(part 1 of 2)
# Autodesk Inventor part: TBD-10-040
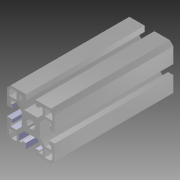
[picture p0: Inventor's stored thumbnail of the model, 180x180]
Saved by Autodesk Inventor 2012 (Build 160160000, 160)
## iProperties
Created: 2004-10
Document SubType Name: Modeling
Designer: Autodesk, Inc.
Manufacturer: Standard
Standards Organization: Custom
Material: Aluminum-6061
Stock Number: 10-040
Description: 40 SERIES, 40X40, STANDARD PROFILE
Catalog Web Link: http://www.parker.com/ead/cm1.asp?cmid=809
Vendor: PARKER IPS
Part Number: TBD-10-040
Mass: 179.948 g
Surface Area: 483.565 cm^2
Volume: 66.4013 cm^3
Density: 2.71 g/cm^3
CAGE: 1LJX3
Dept. ID: Product Design
Description #2: ---
Finish #1: ---
Finish #2: ---
Material ID: ---
Project Number: ---
Length: 100.000 mm
Author: Autodesk, Inc.
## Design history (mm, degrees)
sketch "40 Series Base"
  geometry: L1 (-17, 20)-(17, 20); L2 (20, 17)-(20, -17); L3 (17, -20)-(-17, -20); L4 (-20, -17)-(-20, 17); L5 (-17, 20)-(-20, 17); L6 (17, 20)-(20, 17); L7 (20, -17)-(17, -20); L8 (-17, -20)-(-20, -17); C1 r 3.4 at (0, 0); 7 further points
  constraints: 16 end point, 8 point on line, 2 midpoint, 2 parallel, 1 centre point, 1 horizontal, 1 horizontal alignment, 1 perpendicular, 1 vertical alignment
  dimensions: "Height" = 40 distance of point (-20, -20) point (-20, 20); "Width" = 40 distance of point (-20, 20) point (20, 20); "d9" = 3 distance of L1.start point (-20, 20); "d10" = 3 distance of L4.end point (-20, 20) (= d9); "d11" = 3 distance of L1.end point (20, 20) (= d9); "d12" = 3 distance of L2.start point (20, 20) (= d11); "d13" = 3 distance of L2.end point (20, -20) (= d9); "d14" = 3 distance of L3.start point (20, -20) (= d13); "d15" = 3 distance of L3.end point (-20, -20) (= d9); "d16" = 3 distance of L4.start point (-20, -20) (= d15); "CenterX" = 20 distance from line of C1.centre L4; "CenterY" = 20 distance from line of L3 C1.centre; "Center_Dia" = 6.8 diameter of C1
extrude "Base Extrusion" new body sketch "40 Series Base" taper "d21" = 0 deg; stored distance "Length" = 100
extrude "CenterHole" cut sketch "40 Series Base" stored distance "d22" = 100; taper "d23" = 0 deg
sketch "Sketch5"
  geometry: L1 (17, -20)-(-17, -20) reference; L2 (-20, -17)-(-20, 17) reference; L3 (3.375, -7.75)-(-3.375, -7.75); L4 (4, -15.5)-(10, -15.5); L5 (10, -15.5)-(10, -14.177); L6 (10, -14.177)-(3.375, -7.75); L7 (4, -20)-(4, -15.5); L8 (-4, -20)-(4, -20); L9 (-4, -15.5)-(-4, -20); L10 (-3.375, -7.75)-(-10, -14.177); L11 (-10, -14.177)-(-10, -15.5); L12 (-10, -15.5)-(-4, -15.5); L13 (0, -7.75)-(0, -20)
  constraints: 22 end point, 2 collinear, 2 midpoint, 1 vertical, 3 other
  dimensions: "d24" = 20 distance between parallel lines of L5 L11; "d25" = 6.75 distance of L3.start L3.end; "d26" = 4.5 distance between parallel lines of L8 L12; "d27" = 1.32302 distance of L10.end L11.end; "d28" = 8 distance between parallel lines of L7 L9; "d29" = 20 distance between parallel lines of L13 L2; "d30" = 12.25 distance of L13.start L13.end; "d31" = 4.5 distance between parallel lines of L8 L4 (derived)
extrude "Standard Slot X" cut sketch "Sketch5" stored distance "d32" = 100; taper "d33" = 0 deg
sketch "Sketch6"
  geometry: L1 (-20, -17)-(-20, 17) reference; L2 (17, -20)-(-17, -20) reference; L3 (-20, 4)-(-15.5, 4); L4 (-15.5, 4)-(-15.5, 10); L5 (-15.5, 10)-(-14.177, 10); L6 (-14.177, 10)-(-7.75, 3.375); L7 (-7.75, 3.375)-(-7.75, -3.375); L8 (-7.75, -3.375)-(-14.177, -10); L9 (-14.177, -10)-(-15.5, -10); L10 (-15.5, -10)-(-15.5, -4); L11 (-15.5, -4)-(-20, -4); L12 (-20, 4)-(-20, -4); L13 (-7.75, 0)-(-20, 0)
  constraints: 22 end point, 4 parallel, 2 collinear, 2 midpoint, 2 perpendicular, 2 point on line, 1 horizontal, 3 other
  dimensions: "d34" = 8 distance between parallel lines of L11 L3 (= d28); "d35" = 4.5 distance of L3.start L3.end (= d26); "d36" = 1.32302 distance of L4.end L5.end (= d27); "d37" = 12.25 distance between parallel lines of L12 L7 (= d30); "d38" = 20 distance between parallel lines of L9 L5 (= d24); "d39" = 6.75 distance of L6.end L7.end (= d25); "d40" = 20 distance between parallel lines of L2 L13
extrude "Standard Slot Y" cut sketch "Sketch6" stored distance "d41" = 100; taper "d42" = 0 deg
pattern_linear "Slot X Pattern" dims "d87" = 40
pattern_linear "Slot Y Pattern" dims "d67" = 40
mirror "Mirror Slot X"
mirror "Mirror Slot Y"
pattern_linear "CenterHole Pattern" dims "d70" = 40
sketch "10-040"
  geometry: L1 (16.263, 18.22)-(11.78, 18.22) reference; L2 (11.78, 18.22)-(11.78, 11.78) reference; L3 (11.78, 11.78)-(18.22, 11.78) reference; L4 (18.22, 11.78)-(18.22, 16.263) reference; L5 (18.22, 16.263)-(16.263, 18.22) reference; L6 (16.263, -18.22)-(11.78, -18.22) reference; L7 (11.78, -18.22)-(11.78, -11.78) reference; L8 (11.78, -11.78)-(18.22, -11.78) reference; L9 (18.22, -11.78)-(18.22, -16.263) reference; L10 (18.22, -16.263)-(16.263, -18.22) reference; L11 (7, -17)-(10, -17) reference; L12 (10, -17)-(10, -12.125) reference; L13 (10, -12.125)-(5.625, -7.75) reference; L14 (5.625, -7.75)-(0, -7.75) reference; L15 (0, -7.75)-(-5.625, -7.75) reference; L16 (-5.625, -7.75)-(-10, -12.125) reference; L17 (-10, -12.125)-(-10, -17) reference; L18 (-10, -17)-(-7, -17) reference; L19 (-7, -17)-(-7, -15.5) reference; L20 (-7, -15.5)-(-4, -15.5) reference; L21 (-4, -15.5)-(-4, -20) reference; L22 (-4, -20)-(-17, -20) reference; L23 (-17, -20)-(-20, -17) reference; L24 (-20, -17)-(-20, -4) reference; L25 (-20, -4)-(-15.5, -4) reference; L26 (-15.5, -4)-(-15.5, -7) reference; L27 (-15.5, -7)-(-17, -7) reference; L28 (-17, -7)-(-17, -10) reference; L29 (-17, -10)-(-12.125, -10) reference; L30 (-12.125, -10)-(-7.75, -5.625) reference; L31 (-7.75, -5.625)-(-7.75, 0) reference; L32 (-7.75, 0)-(-7.75, 5.625) reference; L33 (-7.75, 5.625)-(-12.125, 10) reference; L34 (-12.125, 10)-(-17, 10) reference; L35 (-17, 10)-(-17, 7) reference; L36 (-17, 7)-(-15.5, 7) reference; L37 (-15.5, 7)-(-15.5, 4) reference; L38 (-15.5, 4)-(-20, 4) reference; L39 (-20, 4)-(-20, 17) reference; L40 (-20, 17)-(-17, 20) reference; L41 (-17, 20)-(-4, 20) reference; L42 (-4, 20)-(-4, 15.5) reference; L43 (-4, 15.5)-(-7, 15.5) reference; L44 (-7, 15.5)-(-7, 17) reference; L45 (-7, 17)-(-10, 17) reference; L46 (-10, 17)-(-10, 12.125) reference; L47 (-10, 12.125)-(-5.625, 7.75) reference; L48 (-5.625, 7.75)-(0, 7.75) reference; L49 (0, 7.75)-(5.625, 7.75) reference; L50 (5.625, 7.75)-(10, 12.125) reference; L51 (10, 12.125)-(10, 17) reference; L52 (10, 17)-(7, 17) reference; L53 (7, 17)-(7, 15.5) reference; L54 (7, 15.5)-(4, 15.5) reference; L55 (4, 15.5)-(4, 20) reference; L56 (4, 20)-(17, 20) reference; L57 (17, 20)-(20, 17) reference; L58 (20, 17)-(20, 4) reference; L59 (20, 4)-(15.5, 4) reference; L60 (15.5, 4)-(15.5, 7) reference; L61 (15.5, 7)-(17, 7) reference; L62 (17, 7)-(17, 10) reference; L63 (17, 10)-(12.125, 10) reference; L64 (12.125, 10)-(7.75, 5.625) reference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; C1 r 3.4 at (0, 0) reference
  constraints: 176 end point, 36 horizontal, 36 vertical, 1 centre point, 106 other
sketch "10-540"
  geometry: L1 (15.5, -4)-(20, -4) reference; L2 (20, -4)-(20, -17) reference; L3 (20, -17)-(17, -20) reference; L4 (17, -20)-(4, -20) reference; L5 (4, -20)-(4, -15.5) reference; L6 (4, -15.5)-(7, -15.5) reference; L7 (7, -15.5)-(7, -17) reference; L8 (7, -17)-(10, -17) reference; L9 (10, -17)-(10, -13.525) reference; L10 (10, -13.525)-(4.225, -7.75) reference; L11 (4.225, -7.75)-(0, -7.75) reference; L12 (0, -7.75)-(-4.225, -7.75) reference; L13 (-4.225, -7.75)-(-10, -13.525) reference; L14 (-10, -13.525)-(-10, -17) reference; L15 (-10, -17)-(-7, -17) reference; L16 (-7, -17)-(-7, -15.5) reference; L17 (-7, -15.5)-(-4, -15.5) reference; L18 (-4, -15.5)-(-4, -20) reference; L19 (-4, -20)-(-17, -20) reference; L20 (-17, -20)-(-20, -17) reference; L21 (-20, -17)-(-20, -4) reference; L22 (-20, -4)-(-15.5, -4) reference; L23 (-15.5, -4)-(-15.5, -7) reference; L24 (-15.5, -7)-(-17, -7) reference; L25 (-17, -7)-(-17, -10) reference; L26 (-17, -10)-(-13.525, -10) reference; L27 (-13.525, -10)-(-7.75, -4.225) reference; L28 (-7.75, -4.225)-(-7.75, 0) reference; L29 (-7.75, 0)-(-7.75, 4.225) reference; L30 (-7.75, 4.225)-(-13.525, 10) reference; L31 (-13.525, 10)-(-17, 10) reference; L32 (-17, 10)-(-17, 7) reference; L33 (-17, 7)-(-15.5, 7) reference; L34 (-15.5, 7)-(-15.5, 4) reference; L35 (-15.5, 4)-(-20, 4) reference; L36 (-20, 4)-(-20, 17) reference; L37 (-20, 17)-(-17, 20) reference; L38 (-17, 20)-(-4, 20) reference; L39 (-4, 20)-(-4, 15.5) reference; L40 (-4, 15.5)-(-7, 15.5) reference; L41 (-7, 15.5)-(-7, 17) reference; L42 (-7, 17)-(-10, 17) reference; L43 (-10, 17)-(-10, 13.525) reference; L44 (-10, 13.525)-(-4.225, 7.75) reference; L45 (-4.225, 7.75)-(0, 7.75) reference; L46 (0, 7.75)-(4.225, 7.75) reference; L47 (4.225, 7.75)-(10, 13.525) reference; L48 (10, 13.525)-(10, 17) reference; L49 (10, 17)-(7, 17) reference; L50 (7, 17)-(7, 15.5) reference; L51 (7, 15.5)-(4, 15.5) reference; L52 (4, 15.5)-(4, 20) reference; L53 (4, 20)-(17, 20) reference; L54 (17, 20)-(20, 17) reference; L55 (20, 17)-(20, 4) reference; L56 (20, 4)-(15.5, 4) reference; L57 (15.5, 4)-(15.5, 7) reference; L58 (15.5, 7)-(17, 7) reference; L59 (17, 7)-(17, 10) reference; L60 (17, 10)-(13.525, 10) reference; L61 (13.525, 10)-(7.75, 4.225) reference; L62 (7.75, 4.225)-(7.75, 0) reference; L63 (7.75, 0)-(7.75, -4.225) reference; L64 (7.75, -4.225)-(13.525, -10) reference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; C1 r 3.4 at (0, 0) reference
  constraints: 240 end point, 44 horizontal, 44 vertical, 1 centre point, 154 other
extrude "Extrusion 10-040" sketch "10-040" stored distance "d45" = 100; taper "d46" = 0 deg
extrude "Extrusion 10-540" sketch "10-540" stored distance "d47" = 100; taper "d48" = 0 deg
sketch "10-140"
  geometry: L1 (17, 20)-(20, 17) reference; L2 (20, 17)-(20, -17) reference; L3 (20, -17)-(17, -20) reference; L4 (17, -20)-(4, -20) reference; L5 (4, -20)-(4, -15.5) reference; L6 (4, -15.5)-(7, -15.5) reference; L7 (7, -15.5)-(7, -17) reference; L8 (7, -17)-(10, -17) reference; L9 (10, -17)-(10, -12.125) reference; L10 (10, -12.125)-(5.625, -7.75) reference; L11 (5.625, -7.75)-(0, -7.75) reference; L12 (0, -7.75)-(-5.625, -7.75) reference; L13 (-5.625, -7.75)-(-10, -12.125) reference; L14 (-10, -12.125)-(-10, -17) reference; L15 (-10, -17)-(-7, -17) reference; L16 (-7, -17)-(-7, -15.5) reference; L17 (-7, -15.5)-(-4, -15.5) reference; L18 (-4, -15.5)-(-4, -20) reference; L19 (-4, -20)-(-17, -20) reference; L20 (-17, -20)-(-20, -17) reference; L21 (-20, -17)-(-20, -4) reference; L22 (-20, -4)-(-15.5, -4) reference; L23 (-15.5, -4)-(-15.5, -7) reference; L24 (-15.5, -7)-(-17, -7) reference; L25 (-17, -7)-(-17, -10) reference; L26 (-17, -10)-(-12.125, -10) reference; L27 (-12.125, -10)-(-7.75, -5.625) reference; L28 (-7.75, -5.625)-(-7.75, 0) reference; L29 (-7.75, 0)-(-7.75, 5.625) reference; L30 (-7.75, 5.625)-(-12.125, 10) reference; L31 (-12.125, 10)-(-17, 10) reference; L32 (-17, 10)-(-17, 7) reference; L33 (-17, 7)-(-15.5, 7) reference; L34 (-15.5, 7)-(-15.5, 4) reference; L35 (-15.5, 4)-(-20, 4) reference; L36 (-20, 4)-(-20, 17) reference; L37 (-20, 17)-(-17, 20) reference; L38 (-17, 20)-(17, 20) reference; L39 (18.22, -16.263)-(18.22, -9.28) reference; L40 (18.22, -9.28)-(11.78, -9.28) reference; L41 (11.78, -9.28)-(11.78, -18.22) reference; L42 (11.78, -18.22)-(16.263, -18.22) reference; L43 (16.263, -18.22)-(18.22, -16.263) reference; L44 (18.22, 16.263)-(18.22, 9.28) reference; L45 (18.22, 9.28)-(9.28, 9.28) reference; L46 (9.28, 9.28)-(9.28, 18.22) reference; L47 (9.28, 18.22)-(16.263, 18.22) reference; L48 (16.263, 18.22)-(18.22, 16.263) reference; L49 (18.22, 4)-(15.5, 4) reference; L50 (15.5, 4)-(15.5, 7.5) reference; L51 (15.5, 7.5)-(12.75, 7.5) reference; L52 (12.75, 7.5)-(7.75, 2.5) reference; L53 (7.75, 2.5)-(7.75, -2.5) reference; L54 (7.75, -2.5)-(12.75, -7.5) reference; L55 (12.75, -7.5)-(15.5, -7.5) reference; L56 (15.5, -7.5)-(15.5, -4) reference; L57 (15.5, -4)-(18.22, -4) reference; L58 (18.22, -4)-(18.22, 4) reference; L59 (-18.22, 16.263)-(-18.22, 11.78) reference; L60 (-18.22, 11.78)-(-9.28, 11.78) reference; L61 (-9.28, 11.78)-(-9.28, 18.22) reference; L62 (-9.28, 18.22)-(-16.263, 18.22) reference; L63 (-16.263, 18.22)-(-18.22, 16.263) reference; L64 (4, 18.22)-(4, 15.5) reference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; C1 r 3.4 at (0, 0) reference
  constraints: 156 end point, 31 horizontal, 31 vertical, 1 centre point, 96 other
extrude "Extrusion 10-140" sketch "10-140" stored distance "d49" = 10; taper "d50" = 0 deg
sketch "10-240"
  geometry: L1 (-17, -20)-(-4, -20) reference; L2 (-4, -20)-(-4, -15.5) reference; L3 (-4, -15.5)-(-7, -15.5) reference; L4 (-7, -15.5)-(-7, -17) reference; L5 (-7, -17)-(-10, -17) reference; L6 (-10, -17)-(-10, -12.125) reference; L7 (-10, -12.125)-(-5.625, -7.75) reference; L8 (-5.625, -7.75)-(0, -7.75) reference; L9 (0, -7.75)-(5.625, -7.75) reference; L10 (5.625, -7.75)-(10, -12.125) reference; L11 (10, -12.125)-(10, -17) reference; L12 (10, -17)-(7, -17) reference; L13 (7, -17)-(7, -15.5) reference; L14 (7, -15.5)-(4, -15.5) reference; L15 (4, -15.5)-(4, -20) reference; L16 (4, -20)-(17, -20) reference; L17 (17, -20)-(20, -17) reference; L18 (20, -17)-(20, 17) reference; L19 (20, 17)-(17, 20) reference; L20 (17, 20)-(4, 20) reference; L21 (4, 20)-(4, 15.5) reference; L22 (4, 15.5)-(7, 15.5) reference; L23 (7, 15.5)-(7, 17) reference; L24 (7, 17)-(10, 17) reference; L25 (10, 17)-(10, 12.125) reference; L26 (10, 12.125)-(5.625, 7.75) reference; L27 (5.625, 7.75)-(0, 7.75) reference; L28 (0, 7.75)-(-5.625, 7.75) reference; L29 (-5.625, 7.75)-(-10, 12.125) reference; L30 (-10, 12.125)-(-10, 17) reference; L31 (-10, 17)-(-7, 17) reference; L32 (-7, 17)-(-7, 15.5) reference; L33 (-7, 15.5)-(-4, 15.5) reference; L34 (-4, 15.5)-(-4, 20) reference; L35 (-4, 20)-(-17, 20) reference; L36 (-17, 20)-(-20, 17) reference; L37 (-20, 17)-(-20, -17) reference; L38 (-20, -17)-(-17, -20) reference; L39 (-18.22, -16.263)-(-18.22, -9.28) reference; L40 (-18.22, -9.28)-(-11.78, -9.28) reference; L41 (-11.78, -9.28)-(-11.78, -18.22) reference; L42 (-11.78, -18.22)-(-16.263, -18.22) reference; L43 (-16.263, -18.22)-(-18.22, -16.263) reference; L44 (-18.22, 16.263)-(-18.22, 9.28) reference; L45 (-18.22, 9.28)-(-11.78, 9.28) reference; L46 (-11.78, 9.28)-(-11.78, 18.22) reference; L47 (-11.78, 18.22)-(-16.263, 18.22) reference; L48 (-16.263, 18.22)-(-18.22, 16.263) reference; L49 (-18.22, -4)-(-15.5, -4) reference; L50 (-15.5, -4)-(-15.5, -7.5) reference; L51 (-15.5, -7.5)-(-12.75, -7.5) reference; L52 (-12.75, -7.5)-(-7.75, -2.5) reference; L53 (-7.75, -2.5)-(-7.75, 2.5) reference; L54 (-7.75, 2.5)-(-12.75, 7.5) reference; L55 (-12.75, 7.5)-(-15.5, 7.5) reference; L56 (-15.5, 7.5)-(-15.5, 4) reference; L57 (-15.5, 4)-(-18.22, 4) reference; L58 (-18.22, 4)-(-18.22, -4) reference; L59 (18.22, -16.263)-(18.22, -9.28) reference; L60 (18.22, -9.28)-(11.78, -9.28) reference; L61 (11.78, -9.28)-(11.78, -18.22) reference; L62 (11.78, -18.22)-(16.263, -18.22) reference; L63 (16.263, -18.22)-(18.22, -16.263) reference; L64 (18.22, -4)-(15.5, -4) reference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; C1 r 3.4 at (0, 0) reference
  constraints: 156 end point, 32 horizontal, 30 vertical, 1 centre point, 96 other
extrude "Extrusion 10-240" sketch "10-240" stored distance "d51" = 10; taper "d52" = 0 deg
sketch "10-340"
  geometry: L1 (-17, -10)-(-17, -7) reference; L2 (-17, -7)-(-15.5, -7) reference; L3 (-15.5, -7)-(-15.5, -4) reference; L4 (-15.5, -4)-(-20, -4) reference; L5 (-20, -4)-(-20, -17) reference; L6 (-20, -17)-(-17, -20) reference; L7 (-17, -20)-(-4, -20) reference; L8 (-4, -20)-(-4, -15.5) reference; L9 (-4, -15.5)-(-7, -15.5) reference; L10 (-7, -15.5)-(-7, -17) reference; L11 (-7, -17)-(-10, -17) reference; L12 (-10, -17)-(-10, -12.125) reference; L13 (-10, -12.125)-(-5.625, -7.75) reference; L14 (-5.625, -7.75)-(5.625, -7.75) reference; L15 (5.625, -7.75)-(10, -12.125) reference; L16 (10, -12.125)-(10, -17) reference; L17 (10, -17)-(7, -17) reference; L18 (7, -17)-(7, -15.5) reference; L19 (7, -15.5)-(4, -15.5) reference; L20 (4, -15.5)-(4, -20) reference; L21 (4, -20)-(17, -20) reference; L22 (17, -20)-(20, -17) reference; L23 (20, -17)-(20, -4) reference; L24 (20, -4)-(15.5, -4) reference; L25 (15.5, -4)-(15.5, -7) reference; L26 (15.5, -7)-(17, -7) reference; L27 (17, -7)-(17, -10) reference; L28 (17, -10)-(12.125, -10) reference; L29 (12.125, -10)-(7.75, -5.625) reference; L30 (7.75, -5.625)-(7.75, 5.625) reference; L31 (7.75, 5.625)-(12.125, 10) reference; L32 (12.125, 10)-(17, 10) reference; L33 (17, 10)-(17, 7) reference; L34 (17, 7)-(15.5, 7) reference; L35 (15.5, 7)-(15.5, 4) reference; L36 (15.5, 4)-(20, 4) reference; L37 (20, 4)-(20, 17) reference; L38 (20, 17)-(17, 20) reference; L39 (17, 20)-(-17, 20) reference; L40 (-17, 20)-(-20, 17) reference; L41 (-20, 17)-(-20, 4) reference; L42 (-20, 4)-(-15.5, 4) reference; L43 (-15.5, 4)-(-15.5, 7) reference; L44 (-15.5, 7)-(-17, 7) reference; L45 (-17, 7)-(-17, 10) reference; L46 (-17, 10)-(-12.125, 10) reference; L47 (-12.125, 10)-(-7.75, 5.625) reference; L48 (-7.75, 5.625)-(-7.75, -5.625) reference; L49 (-7.75, -5.625)-(-12.125, -10) reference; L50 (-12.125, -10)-(-17, -10) reference; L51 (-4, 18.22)-(-4, 15.5) reference; L52 (-4, 15.5)-(-7.5, 15.5) reference; L53 (-7.5, 15.5)-(-7.5, 12.75) reference; L54 (-7.5, 12.75)-(-2.5, 7.75) reference; L55 (-2.5, 7.75)-(2.5, 7.75) reference; L56 (2.5, 7.75)-(7.5, 12.75) reference; L57 (7.5, 12.75)-(7.5, 15.5) reference; L58 (7.5, 15.5)-(4, 15.5) reference; L59 (4, 15.5)-(4, 18.22) reference; L60 (4, 18.22)-(-4, 18.22) reference; L61 (-16.263, -18.22)-(-11.78, -18.22) reference; L62 (-11.78, -18.22)-(-11.78, -11.78) reference; L63 (-11.78, -11.78)-(-18.22, -11.78) reference; L64 (-18.22, -11.78)-(-18.22, -16.263) reference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; C1 r 3.4 at (0, 0) reference
  constraints: 160 end point, 32 horizontal, 32 vertical, 1 centre point, 98 other
extrude "Extrusion 10-340" sketch "10-340" stored distance "d53" = 10; taper "d54" = 0 deg
sketch "10-440"
  geometry: L1 (-1.542, -7.75)-(1.542, -7.75) reference; L2 (5.625, -7.75)-(0, -7.75) reference; L3 (0, -7.75)-(-5.625, -7.75) reference; L4 (-5.625, -7.75)-(-10, -12.125) reference; L5 (-10, -12.125)-(-10, -17) reference; L6 (-10, -17)-(-7, -17) reference; L7 (-7, -17)-(-7, -15.5) reference; L8 (-7, -15.5)-(-4, -15.5) reference; L9 (-4, -15.5)-(-4, -20) reference; L10 (-4, -20)-(-17, -20) reference; L11 (-17, -20)-(-20, -17) reference; L12 (-20, -17)-(-20, 17) reference; L13 (-20, 17)-(-17, 20) reference; L14 (-17, 20)-(17, 20) reference; L15 (17, 20)-(20, 17) reference; L16 (20, 17)-(20, -17) reference; L17 (20, -17)-(17, -20) reference; L18 (17, -20)-(4, -20) reference; L19 (4, -20)-(4, -15.5) reference; L20 (4, -15.5)-(7, -15.5) reference; L21 (7, -15.5)-(7, -17) reference; L22 (7, -17)-(10, -17) reference; L23 (10, -17)-(10, -12.125) reference; L24 (10, -12.125)-(5.625, -7.75) reference; L25 (-16.172, -18)-(-18, -16.172) reference; L26 (-18, -16.172)-(-18, -1) reference; L27 (-18, -1)-(-7.974, -1) reference; L28 (-7.974, -1)-(-6.57, -4.39) reference; L29 (-6.57, -4.39)-(-5.21, -5.75) reference; L30 (-5.21, -5.75)-(-6.453, -5.75) reference; L31 (-6.453, -5.75)-(-12, -11.297) reference; L32 (-12, -11.297)-(-12, -18) reference; L33 (-12, -18)-(-16.172, -18) reference; L34 (-16.172, 18)-(-1, 18) reference; L35 (-1, 18)-(-1, 7.974) reference; L36 (-1, 7.974)-(-4.39, 6.57) reference; L37 (-4.39, 6.57)-(-6.57, 4.39) reference; L38 (-6.57, 4.39)-(-7.974, 1) reference; L39 (-7.974, 1)-(-18, 1) reference; L40 (-18, 1)-(-18, 16.172) reference; L41 (-18, 16.172)-(-16.172, 18) reference; L42 (12, -11.297)-(6.453, -5.75) reference; L43 (6.453, -5.75)-(5.21, -5.75) reference; L44 (5.21, -5.75)-(6.57, -4.39) reference; L45 (6.57, -4.39)-(7.974, -1) reference; L46 (7.974, -1)-(18, -1) reference; L47 (18, -1)-(18, -16.172) reference; L48 (18, -16.172)-(16.172, -18) reference; L49 (16.172, -18)-(12, -18) reference; L50 (12, -18)-(12, -11.297) reference; L51 (18, 16.172)-(18, 1) reference; L52 (18, 1)-(7.974, 1) reference; L53 (7.974, 1)-(6.57, 4.39) reference; L54 (6.57, 4.39)-(4.39, 6.57) reference; L55 (4.39, 6.57)-(1, 7.974) reference; L56 (1, 7.974)-(1, 18) reference; L57 (1, 18)-(16.172, 18) reference; L58 (16.172, 18)-(18, 16.172) reference; C1 r 3.4 at (0, 0) reference
  constraints: 116 end point, 20 horizontal, 16 vertical, 2 point on line, 1 centre point, 1 midpoint, 83 other
extrude "Extrusion 10-440" sketch "10-440" stored distance "d55" = 10; taper "d56" = 0 deg
sketch "10-043"
  geometry: L1 (11.78, -18.22)-(11.78, -9.53) reference; L2 (11.78, -9.53)-(16.737, -9.53) reference; L3 (18.013, -16.47)-(16.263, -18.22) reference; L4 (16.263, -18.22)-(11.78, -18.22) reference; L5 (-18.22, -16.263)-(-18.22, -11.78) reference; L6 (-18.22, -11.78)-(-11.78, -11.78) reference; L7 (-11.78, -11.78)-(-11.78, -18.22) reference; L8 (-11.78, -18.22)-(-16.263, -18.22) reference; L9 (-16.263, -18.22)-(-18.22, -16.263) reference; L10 (19.877, -17.123)-(17, -20) reference; L11 (17, -20)-(4, -20) reference; L12 (4, -20)-(4, -15.5) reference; L13 (4, -15.5)-(7, -15.5) reference; L14 (7, -15.5)-(7, -17) reference; L15 (7, -17)-(10, -17) reference; L16 (10, -17)-(10, -12.125) reference; L17 (10, -12.125)-(5.625, -7.75) reference; L18 (5.625, -7.75)-(0, -7.75) reference; L19 (0, -7.75)-(-5.625, -7.75) reference; L20 (-5.625, -7.75)-(-10, -12.125) reference; L21 (-10, -12.125)-(-10, -17) reference; L22 (-10, -17)-(-7, -17) reference; L23 (-7, -17)-(-7, -15.5) reference; L24 (-7, -15.5)-(-4, -15.5) reference; L25 (-4, -15.5)-(-4, -20) reference; L26 (-4, -20)-(-17, -20) reference; L27 (-17, -20)-(-20, -17) reference; L28 (-20, -17)-(-20, -4) reference; L29 (-20, -4)-(-15.5, -4) reference; L30 (-15.5, -4)-(-15.5, -7) reference; L31 (-15.5, -7)-(-17, -7) reference; L32 (-17, -7)-(-17, -10) reference; L33 (-17, -10)-(-12.125, -10) reference; L34 (-12.125, -10)-(-7.75, -5.625) reference; L35 (-7.75, -5.625)-(-7.75, 0) reference; L36 (-7.75, 0)-(-7.75, 5.625) reference; L37 (-7.75, 5.625)-(-12.125, 10) reference; L38 (-12.125, 10)-(-17, 10) reference; L39 (-17, 10)-(-17, 7) reference; L40 (-17, 7)-(-15.5, 7) reference; L41 (-15.5, 7)-(-15.5, 4) reference; L42 (-15.5, 4)-(-20, 4) reference; L43 (-20, 4)-(-20, 17) reference; L44 (-20, 17)-(-17.123, 19.877) reference; L45 (-17.123, 19.877)-(-16.862, 19.877) reference; L46 (16.188, -7.75)-(7.25, -7.75) reference; L47 (7.25, -7.75)-(7.338, 6.722) reference; L48 (6.812, 7.25)-(-7.75, 7.25) reference; L49 (-7.75, 7.25)-(-7.75, 16.188) reference; L50 (-16.47, 18.013)-(-18.22, 16.263) reference; L51 (-18.22, 16.263)-(-18.22, 11.78) reference; L52 (-18.22, 11.78)-(-9.53, 11.78) reference; L53 (-9.53, 11.78)-(-9.53, 16.737) reference; C1 r 3.4 at (0, 0) reference; A1 r 40 centre (-20.02, -19.998) between (19.877, -17.123) and (-16.862, 19.877); A2 r 38 centre (-19.838, -19.838) between (-9.53, 16.737) and (-16.47, 18.013) reference; A3 r 38 centre (-19.838, -19.838) between (6.812, 7.25) and (-7.75, 16.188) reference; A4 r 38 centre (-19.838, -19.838) between (18.013, -16.47) and (16.737, -9.53); A5 r 38 centre (-19.838, -19.838) between (16.188, -7.75) and (7.338, 6.722) reference
  constraints: 106 end point, 22 horizontal, 20 vertical, 10 point on circle, 6 centre point, 68 other
  dimensions: "d59" = 40 radius of A1
extrude "Extrusion 10-043" sketch "10-043" stored distance "d57" = 10; taper "d58" = 0 deg
sketch "10-044"
  geometry: L1 (7.25, -5.121)-(9.879, -7.75); L2 (9.879, -7.75)-(16.95, -7.75); L3 (16.95, -7.75)-(7.25, 1.95); L4 (7.25, 1.95)-(7.25, -5.121); L5 (-15.5, -4)-(-20, -4); L6 (-20, -4)-(-20, -17); L7 (-20, -17)-(-17, -20); L8 (-17, -20)-(-4, -20); L9 (-4, -20)-(-4, -15.5); L10 (-4, -15.5)-(-7, -15.5); L11 (-7, -15.5)-(-7, -17); L12 (-7, -17)-(-10, -17); L13 (-10, -17)-(-10, -12.125); L14 (-10, -12.125)-(-5.625, -7.75); L15 (-5.625, -7.75)-(0, -7.75); L16 (0, -7.75)-(5.625, -7.75); L17 (5.625, -7.75)-(10, -12.125); L18 (10, -12.125)-(10, -17); L19 (10, -17)-(7, -17); L20 (7, -17)-(7, -15.5); L21 (7, -15.5)-(4, -15.5); L22 (4, -15.5)-(4, -20); L23 (4, -20)-(17, -20); L24 (17, -20)-(20, -17); L25 (20, -17)-(20, -8.282); L26 (20, -8.282)-(-8.282, 20); L27 (-8.282, 20)-(-17, 20); L28 (-17, 20)-(-20, 17); L29 (-20, 17)-(-20, 4); L30 (-20, 4)-(-15.5, 4); L31 (-15.5, 4)-(-15.5, 7); L32 (-15.5, 7)-(-17, 7); L33 (-17, 7)-(-17, 10); L34 (-17, 10)-(-12.125, 10); L35 (-12.125, 10)-(-7.75, 5.625); L36 (-7.75, 5.625)-(-7.75, 0); L37 (-7.75, 0)-(-7.75, -5.625); L38 (-7.75, -5.625)-(-12.125, -10); L39 (-12.125, -10)-(-17, -10); L40 (-17, -10)-(-17, -7); L41 (-17, -7)-(-15.5, -7); L42 (-15.5, -7)-(-15.5, -4); L43 (-5.121, 7.25)-(-7.75, 9.879); L44 (-7.75, 9.879)-(-7.75, 16.95); L45 (-7.75, 16.95)-(1.95, 7.25); L46 (1.95, 7.25)-(-5.121, 7.25); L47 (-18.22, 16.263)-(-18.22, 11.78); L48 (-18.22, 11.78)-(-9.53, 11.78); L49 (-9.53, 11.78)-(-9.53, 18.22); L50 (-9.53, 18.22)-(-16.263, 18.22); L51 (-16.263, 18.22)-(-18.22, 16.263); L52 (-11.78, -18.22)-(-11.78, -11.78); L53 (-11.78, -11.78)-(-18.22, -11.78); L54 (-18.22, -11.78)-(-18.22, -16.263); L55 (-18.22, -16.263)-(-16.263, -18.22); L56 (-16.263, -18.22)-(-11.78, -18.22); L57 (16.263, -18.22)-(11.78, -18.22); L58 (11.78, -18.22)-(11.78, -9.53); L59 (11.78, -9.53)-(18.22, -9.53); L60 (18.22, -9.53)-(18.22, -16.263); L61 (18.22, -16.263)-(16.263, -18.22); C1 r 3.4 at (0, 0)
  constraints: 122 end point, 1 centre point
extrude "Extrusion 10-044" sketch "10-044" stored distance "d61" = 10; taper "d62" = 0 deg
sketch "11-044"
  geometry: L1 (-8.333, 20)-(20, -8.333) reference; L2 (20, -8.333)-(20, -17) reference; L3 (20, -17)-(17, -20) reference; L4 (17, -20)-(4, -20) reference; L5 (4, -20)-(4, -15.5) reference; L6 (4, -15.5)-(10, -15.5) reference; L7 (10, -15.5)-(10, -14.177) reference; L8 (10, -14.177)-(3.374, -7.75) reference; L9 (3.374, -7.75)-(-3.374, -7.75) reference; L10 (-3.374, -7.75)-(-10, -14.177) reference; L11 (-10, -14.177)-(-10, -15.5) reference; L12 (-10, -15.5)-(-4, -15.5) reference; L13 (-4, -15.5)-(-4, -20) reference; L14 (-4, -20)-(-17, -20) reference; L15 (-17, -20)-(-20, -17) reference; L16 (-20, -17)-(-20, -4) reference; L17 (-20, -4)-(-15.5, -4) reference; L18 (-15.5, -4)-(-15.5, -10) reference; L19 (-15.5, -10)-(-14.177, -10) reference; L20 (-14.177, -10)-(-7.75, -3.374) reference; L21 (-7.75, -3.374)-(-7.75, 3.374) reference; L22 (-7.75, 3.374)-(-14.177, 10) reference; L23 (-14.177, 10)-(-15.5, 10) reference; L24 (-15.5, 10)-(-15.5, 4) reference; L25 (-15.5, 4)-(-20, 4) reference; L26 (-20, 4)-(-20, 17) reference; L27 (-20, 17)-(-17, 20) reference; L28 (-17, 20)-(-8.333, 20) reference; L29 (-6.124, 7.75)-(-13.874, 15.5) reference; L30 (-13.874, 15.5)-(-8.217, 15.5) reference; L31 (-8.217, 15.5)-(-0.467, 7.75) reference; L32 (-0.467, 7.75)-(-6.124, 7.75) reference; L33 (7.75, -6.124)-(15.5, -13.874) reference; L34 (15.5, -13.874)-(15.5, -8.217) reference; L35 (15.5, -8.217)-(7.75, -0.467) reference; L36 (7.75, -0.467)-(7.75, -6.124) reference; C1 r 3.4 at (0, 0) reference
  constraints: 72 end point, 12 horizontal, 12 vertical, 1 centre point, 50 other
extrude "Extrusion 11-044" sketch "11-044" stored distance "d63" = 10; taper "d64" = 0 deg
sketch "11-080"
  geometry: L1 (-7.75, 23.374)-(-14.177, 30) reference; L2 (-14.177, 30)-(-15.5, 30) reference; L3 (-15.5, 30)-(-15.5, 24) reference; L4 (-15.5, 24)-(-20, 24) reference; L5 (-20, 24)-(-20, 37) reference; L6 (-20, 37)-(-17, 40) reference; L7 (-17, 40)-(-4, 40) reference; L8 (-4, 40)-(-4, 35.5) reference; L9 (-4, 35.5)-(-10, 35.5) reference; L10 (-10, 35.5)-(-10, 34.177) reference; L11 (-10, 34.177)-(-3.374, 27.75) reference; L12 (-3.374, 27.75)-(3.374, 27.75) reference; L13 (3.374, 27.75)-(10, 34.177) reference; L14 (10, 34.177)-(10, 35.5) reference; L15 (10, 35.5)-(4, 35.5) reference; L16 (4, 35.5)-(4, 40) reference; L17 (4, 40)-(17, 40) reference; L18 (17, 40)-(20, 37) reference; L19 (20, 37)-(20, 24) reference; L20 (20, 24)-(15.5, 24) reference; L21 (15.5, 24)-(15.5, 30) reference; L22 (15.5, 30)-(14.177, 30) reference; L23 (14.177, 30)-(7.75, 23.374) reference; L24 (7.75, 23.374)-(7.75, 16.626) reference; L25 (7.75, 16.626)-(14.177, 10) reference; L26 (14.177, 10)-(15.5, 10) reference; L27 (15.5, 10)-(15.5, 16) reference; L28 (15.5, 16)-(20, 16) reference; L29 (20, 16)-(20, -16) reference; L30 (20, -16)-(15.5, -16) reference; L31 (15.5, -16)-(15.5, -10) reference; L32 (15.5, -10)-(14.177, -10) reference; L33 (14.177, -10)-(7.75, -16.626) reference; L34 (7.75, -16.626)-(7.75, -23.374) reference; L35 (7.75, -23.374)-(14.177, -30) reference; L36 (14.177, -30)-(15.5, -30) reference; L37 (15.5, -30)-(15.5, -24) reference; L38 (15.5, -24)-(20, -24) reference; L39 (20, -24)-(20, -37) reference; L40 (20, -37)-(17, -40) reference; L41 (17, -40)-(4, -40) reference; L42 (4, -40)-(4, -35.5) reference; L43 (4, -35.5)-(10, -35.5) reference; L44 (10, -35.5)-(10, -34.177) reference; L45 (10, -34.177)-(3.374, -27.75) reference; L46 (3.374, -27.75)-(-3.374, -27.75) reference; L47 (-3.374, -27.75)-(-10, -34.177) reference; L48 (-10, -34.177)-(-10, -35.5) reference; L49 (-10, -35.5)-(-4, -35.5) reference; L50 (-4, -35.5)-(-4, -40) reference; L51 (-4, -40)-(-17, -40) reference; L52 (-17, -40)-(-20, -37) reference; L53 (-20, -37)-(-20, -24) reference; L54 (-20, -24)-(-15.5, -24) reference; L55 (-15.5, -24)-(-15.5, -30) reference; L56 (-15.5, -30)-(-14.177, -30) reference; L57 (-14.177, -30)-(-7.75, -23.374) reference; L58 (-7.75, -23.374)-(-7.75, -16.626) reference; L59 (-7.75, -16.626)-(-14.177, -10) reference; L60 (-14.177, -10)-(-15.5, -10) reference; L61 (-15.5, -10)-(-15.5, -16) reference; L62 (-15.5, -16)-(-20, -16) reference; L63 (-20, -16)-(-20, 16) reference; L64 (-20, 16)-(-15.5, 16) reference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; C1 r 3.4 at (0, -20) reference; C2 r 3.4 at (0, 20) reference; 1 further point
  constraints: 176 end point, 32 horizontal, 32 vertical, 2 centre point, 117 other
extrude "Extrusion 11-080" sketch "11-080" stored distance "d71" = 10; taper "d72" = 0 deg
sketch "10-080"
  geometry: L1 (18, -32)-(12, -32) reference; L2 (12, -32)-(12, -38) reference; L3 (12, -38)-(16.172, -38) reference; L4 (16.172, -38)-(18, -36.172) reference; L5 (18, -36.172)-(18, -32) reference; L6 (-16.172, -38)-(-12, -38) reference; L7 (-12, -38)-(-12, -32) reference; L8 (-12, -32)-(-18, -32) reference; L9 (-18, -32)-(-18, -36.172) reference; L10 (-18, -36.172)-(-16.172, -38) reference; L11 (-17, -40)-(-4, -40) reference; L12 (-4, -40)-(-4, -35.5) reference; L13 (-4, -35.5)-(-7, -35.5) reference; L14 (-7, -35.5)-(-7, -37) reference; L15 (-7, -37)-(-10, -37) reference; L16 (-10, -37)-(-10, -32.125) reference; L17 (-10, -32.125)-(-5.625, -27.75) reference; L18 (-5.625, -27.75)-(0, -27.75) reference; L19 (0, -27.75)-(5.625, -27.75) reference; L20 (5.625, -27.75)-(10, -32.125) reference; L21 (10, -32.125)-(10, -37) reference; L22 (10, -37)-(7, -37) reference; L23 (7, -37)-(7, -35.5) reference; L24 (7, -35.5)-(4, -35.5) reference; L25 (4, -35.5)-(4, -40) reference; L26 (4, -40)-(17, -40) reference; L27 (17, -40)-(20, -37) reference; L28 (20, -37)-(20, -24) reference; L29 (20, -24)-(15.5, -24) reference; L30 (15.5, -24)-(15.5, -27) reference; L31 (15.5, -27)-(17, -27) reference; L32 (17, -27)-(17, -30) reference; L33 (17, -30)-(12.125, -30) reference; L34 (12.125, -30)-(7.75, -25.625) reference; L35 (7.75, -25.625)-(7.75, -20) reference; L36 (7.75, -20)-(7.75, -14.375) reference; L37 (7.75, -14.375)-(12.125, -10) reference; L38 (12.125, -10)-(17, -10) reference; L39 (17, -10)-(17, -13) reference; L40 (17, -13)-(15.5, -13) reference; L41 (15.5, -13)-(15.5, -16) reference; L42 (15.5, -16)-(20, -16) reference; L43 (20, -16)-(20, 16) reference; L44 (20, 16)-(15.5, 16) reference; L45 (15.5, 16)-(15.5, 13) reference; L46 (15.5, 13)-(17, 13) reference; L47 (17, 13)-(17, 10) reference; L48 (17, 10)-(12.125, 10) reference; L49 (12.125, 10)-(7.75, 14.375) reference; L50 (7.75, 14.375)-(7.75, 20) reference; L51 (7.75, 20)-(7.75, 25.625) reference; L52 (7.75, 25.625)-(12.125, 30) reference; L53 (12.125, 30)-(17, 30) reference; L54 (17, 30)-(17, 27) reference; L55 (17, 27)-(15.5, 27) reference; L56 (15.5, 27)-(15.5, 24) reference; L57 (15.5, 24)-(20, 24) reference; L58 (20, 24)-(20, 37) reference; L59 (20, 37)-(17, 40) reference; L60 (17, 40)-(4, 40) reference; L61 (4, 40)-(4, 35.5) reference; L62 (4, 35.5)-(7, 35.5) reference; L63 (7, 35.5)-(7, 37) reference; L64 (7, 37)-(10, 37) reference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; C1 r 3.4 at (0, -20) reference; C2 r 3.4 at (0, 20) reference; 1 further point
  constraints: 260 end point, 54 horizontal, 52 vertical, 2 centre point, 159 other
extrude "Extrusion 10-080" sketch "10-080" stored distance "d73" = 10; taper "d74" = 0 deg
sketch "10-680"
  geometry: L1 (12.904, 8.5)-(18, 8.5); L2 (18, 8.5)-(18, -8.5); L3 (18, -8.5)-(12.904, -8.5); L4 (12.904, -8.5)-(6.25, -15.154); L5 (6.25, -15.154)-(6.25, -18.5); L6 (6.25, -18.5)-(5, -18.5); L7 (5, -18.5)-(5, -18.375); L8 (5, -18.375)-(3.09, -15.747); L9 (3.09, -15.747)-(0, -14.743); L10 (0, -14.743)-(-3.09, -15.747); L11 (-3.09, -15.747)-(-5, -18.375); L12 (-5, -18.375)-(-5, -18.5); L13 (-5, -18.5)-(-6.25, -18.5); L14 (-6.25, -18.5)-(-6.25, -15.154); L15 (-6.25, -15.154)-(-12.904, -8.5); L16 (-12.904, -8.5)-(-18, -8.5); L17 (-18, -8.5)-(-18, 8.5); L18 (-18, 8.5)-(-12.904, 8.5); L19 (-12.904, 8.5)-(-6.25, 15.154); L20 (-6.25, 15.154)-(-6.25, 18.5); L21 (-6.25, 18.5)-(-5, 18.5); L22 (-5, 18.5)-(-5, 18.375); L23 (-5, 18.375)-(-3.09, 15.747); L24 (-3.09, 15.747)-(0, 14.743); L25 (0, 14.743)-(3.09, 15.747); L26 (3.09, 15.747)-(5, 18.375); L27 (5, 18.375)-(5, 18.5); L28 (5, 18.5)-(6.25, 18.5); L29 (6.25, 18.5)-(6.25, 15.154); L30 (6.25, 15.154)-(12.904, 8.5); L31 (17, -10)-(13.525, -10); L32 (13.525, -10)-(7.75, -15.775); L33 (7.75, -15.775)-(7.75, -20); L34 (7.75, -20)-(7.75, -24.225); L35 (7.75, -24.225)-(13.525, -30); L36 (13.525, -30)-(17, -30); L37 (17, -30)-(17, -27); L38 (17, -27)-(15.5, -27); L39 (15.5, -27)-(15.5, -24); L40 (15.5, -24)-(20, -24); L41 (20, -24)-(20, -37); L42 (20, -37)-(17, -40); L43 (17, -40)-(4, -40); L44 (4, -40)-(4, -35.5); L45 (4, -35.5)-(7, -35.5); L46 (7, -35.5)-(7, -37); L47 (7, -37)-(10, -37); L48 (10, -37)-(10, -33.525); L49 (10, -33.525)-(4.225, -27.75); L50 (4.225, -27.75)-(0, -27.75); L51 (0, -27.75)-(-4.225, -27.75); L52 (-4.225, -27.75)-(-10, -33.525); L53 (-10, -33.525)-(-10, -37); L54 (-10, -37)-(-7, -37); L55 (-7, -37)-(-7, -35.5); L56 (-7, -35.5)-(-4, -35.5); L57 (-4, -35.5)-(-4, -40); L58 (-4, -40)-(-17, -40); L59 (-17, -40)-(-20, -37); L60 (-20, -37)-(-20, -24); L61 (-20, -24)-(-15.5, -24); L62 (-15.5, -24)-(-15.5, -27); L63 (-15.5, -27)-(-17, -27); L64 (-17, -27)-(-17, -30)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; C1 r 3.4 at (0, -20); C2 r 3.4 at (0, 20); 1 further point
  constraints: 360 end point, 2 centre point
extrude "Extrusion 10-680" sketch "10-680" stored distance "d75" = 10; taper "d76" = 0 deg
sketch "10-180"
  geometry: L1 (11.78, 40)-(-11.78, 40); L2 (-10, 38.22)-(-10, 32.125); L3 (-10, 32.125)-(-5.625, 27.75); L4 (-5.625, 27.75)-(0, 27.75); L5 (0, 27.75)-(5.625, 27.75); L6 (5.625, 27.75)-(10, 32.125); L7 (10, 32.125)-(10, 38.22); L8 (10, 38.22)-(-10, 38.22); L9 (-17, -27)-(-15.5, -27); L10 (-15.5, -27)-(-15.5, -24); L11 (-15.5, -24)-(-20, -24); L12 (-20, -24)-(-20, -37); L13 (-20, -37)-(-17, -40); L14 (-17, -40)-(-4, -40); L15 (-4, -40)-(-4, -35.5); L16 (-4, -35.5)-(-7, -35.5); L17 (-7, -35.5)-(-7, -37); L18 (-7, -37)-(-10, -37); L19 (-10, -37)-(-10, -32.125); L20 (-10, -32.125)-(-5.625, -27.75); L21 (-5.625, -27.75)-(0, -27.75); L22 (0, -27.75)-(5.625, -27.75); L23 (5.625, -27.75)-(10, -32.125); L24 (10, -32.125)-(10, -37); L25 (10, -37)-(7, -37); L26 (7, -37)-(7, -35.5); L27 (7, -35.5)-(4, -35.5); L28 (4, -35.5)-(4, -40); L29 (4, -40)-(17, -40); L30 (17, -40)-(20, -37); L31 (20, -37)-(20, 37); L32 (20, 37)-(17, 40); L33 (17, 40)-(-17, 40); L34 (-17, 40)-(-20, 37); L35 (-20, 37)-(-20, 24); L36 (-20, 24)-(-15.5, 24); L37 (-15.5, 24)-(-15.5, 27); L38 (-15.5, 27)-(-17, 27); L39 (-17, 27)-(-17, 30); L40 (-17, 30)-(-12.125, 30); L41 (-12.125, 30)-(-7.75, 25.625); L42 (-7.75, 25.625)-(-7.75, 20); L43 (-7.75, 20)-(-7.75, 14.375); L44 (-7.75, 14.375)-(-12.125, 10); L45 (-12.125, 10)-(-17, 10); L46 (-17, 10)-(-17, 13); L47 (-17, 13)-(-15.5, 13); L48 (-15.5, 13)-(-15.5, 16); L49 (-15.5, 16)-(-20, 16); L50 (-20, 16)-(-20, -16); L51 (-20, -16)-(-15.5, -16); L52 (-15.5, -16)-(-15.5, -13); L53 (-15.5, -13)-(-17, -13); L54 (-17, -13)-(-17, -10); L55 (-17, -10)-(-12.125, -10); L56 (-12.125, -10)-(-7.75, -14.375); L57 (-7.75, -14.375)-(-7.75, -20); L58 (-7.75, -20)-(-7.75, -25.625); L59 (-7.75, -25.625)-(-12.125, -30); L60 (-12.125, -30)-(-17, -30); L61 (-17, -30)-(-17, -27); L62 (-7.047, 12.25)-(7.047, 12.25); L63 (7.047, 12.25)-(11.297, 8); L64 (11.297, 8)-(18, 8)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; C1 r 3.4 at (0, 20); C2 r 3.4 at (0, -20); 1 further point
  constraints: 200 end point, 2 centre point, 2 point on line, 1 midpoint
extrude "Extrusion 10-180" sketch "10-180" stored distance "d77" = 10; taper "d78" = 0 deg
sketch "10-120"
  geometry: L1 (7.75, 5.625)-(12.125, 10) reference; L2 (12.125, 10)-(17, 10) reference; L3 (17, 10)-(17, 7) reference; L4 (17, 7)-(15.5, 7) reference; L5 (15.5, 7)-(15.5, 4) reference; L6 (15.5, 4)-(20, 4) reference; L7 (20, 4)-(20, 36) reference; L8 (20, 36)-(15.5, 36) reference; L9 (15.5, 36)-(15.5, 33) reference; L10 (15.5, 33)-(17, 33) reference; L11 (17, 33)-(17, 30) reference; L12 (17, 30)-(12.125, 30) reference; L13 (12.125, 30)-(7.75, 34.375) reference; L14 (7.75, 34.375)-(7.75, 40) reference; L15 (7.75, 40)-(7.75, 45.625) reference; L16 (7.75, 45.625)-(12.125, 50) reference; L17 (12.125, 50)-(17, 50) reference; L18 (17, 50)-(17, 47) reference; L19 (17, 47)-(15.5, 47) reference; L20 (15.5, 47)-(15.5, 44) reference; L21 (15.5, 44)-(20, 44) reference; L22 (20, 44)-(20, 57) reference; L23 (20, 57)-(17, 60) reference; L24 (17, 60)-(4, 60) reference; L25 (4, 60)-(4, 55.5) reference; L26 (4, 55.5)-(7, 55.5) reference; L27 (7, 55.5)-(7, 57) reference; L28 (7, 57)-(10, 57) reference; L29 (10, 57)-(10, 52.125) reference; L30 (10, 52.125)-(5.625, 47.75) reference; L31 (5.625, 47.75)-(0, 47.75) reference; L32 (0, 47.75)-(-5.625, 47.75) reference; L33 (-5.625, 47.75)-(-10, 52.125) reference; L34 (-10, 52.125)-(-10, 57) reference; L35 (-10, 57)-(-7, 57) reference; L36 (-7, 57)-(-7, 55.5) reference; L37 (-7, 55.5)-(-4, 55.5) reference; L38 (-4, 55.5)-(-4, 60) reference; L39 (-4, 60)-(-17, 60) reference; L40 (-17, 60)-(-20, 57) reference; L41 (-20, 57)-(-20, 44) reference; L42 (-20, 44)-(-15.5, 44) reference; L43 (-15.5, 44)-(-15.5, 47) reference; L44 (-15.5, 47)-(-17, 47) reference; L45 (-17, 47)-(-17, 50) reference; L46 (-17, 50)-(-12.125, 50) reference; L47 (-12.125, 50)-(-7.75, 45.625) reference; L48 (-7.75, 45.625)-(-7.75, 40) reference; L49 (-7.75, 40)-(-7.75, 34.375) reference; L50 (-7.75, 34.375)-(-12.125, 30) reference; L51 (-12.125, 30)-(-17, 30) reference; L52 (-17, 30)-(-17, 33) reference; L53 (-17, 33)-(-15.5, 33) reference; L54 (-15.5, 33)-(-15.5, 36) reference; L55 (-15.5, 36)-(-20, 36) reference; L56 (-20, 36)-(-20, 4) reference; L57 (-20, 4)-(-15.5, 4) reference; L58 (-15.5, 4)-(-15.5, 7) reference; L59 (-15.5, 7)-(-17, 7) reference; L60 (-17, 7)-(-17, 10) reference; L61 (-17, 10)-(-12.125, 10) reference; L62 (-12.125, 10)-(-7.75, 5.625) reference; L63 (-7.75, 5.625)-(-7.75, 0) reference; L64 (-7.75, 0)-(-7.75, -5.625) reference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; C1 r 3.4 at (0, -40) reference; C2 r 3.4 at (0, 0) reference; C3 r 3.4 at (0, 0) reference; C4 r 3.4 at (0, 40) reference; 1 further point
  constraints: 346 end point, 74 horizontal, 67 vertical, 4 centre point, 2 point on line, 1 midpoint, 215 other
extrude "Extrusion 10-120" sketch "10-120" stored distance "d79" = 10; taper "d80" = 0 deg
sketch "11-140"
  geometry: L1 (-16.086, 1.044)-(-16.086, -1.044) reference; L2 (-16.086, -1.044)-(-4.018, -12.75) reference; L3 (-4.018, -12.75)-(3.002, -12.75) reference; L4 (3.002, -12.75)-(15.07, -1.044) reference; L5 (15.07, -1.044)-(15.07, 1.044) reference; L6 (15.07, 1.044)-(3.002, 12.75) reference; L7 (3.002, 12.75)-(-4.018, 12.75) reference; L8 (-4.018, 12.75)-(-16.086, 1.044) reference; L9 (-7.75, -56.626)-(-7.75, -63.374) reference; L10 (-7.75, -63.374)-(-14.177, -70) reference; L11 (-14.177, -70)-(-15.5, -70) reference; L12 (-15.5, -70)-(-15.5, -64) reference; L13 (-15.5, -64)-(-20, -64) reference; L14 (-20, -64)-(-20, -77) reference; L15 (-20, -77)-(-17, -80) reference; L16 (-17, -80)-(-4, -80) reference; L17 (-4, -80)-(-4, -75.5) reference; L18 (-4, -75.5)-(-10, -75.5) reference; L19 (-10, -75.5)-(-10, -74.177) reference; L20 (-10, -74.177)-(-3.374, -67.75) reference; L21 (-3.374, -67.75)-(3.374, -67.75) reference; L22 (3.374, -67.75)-(10, -74.177) reference; L23 (10, -74.177)-(10, -75.5) reference; L24 (10, -75.5)-(4, -75.5) reference; L25 (4, -75.5)-(4, -80) reference; L26 (4, -80)-(17, -80) reference; L27 (17, -80)-(20, -77) reference; L28 (20, -77)-(20, -64) reference; L29 (20, -64)-(15.5, -64) reference; L30 (15.5, -64)-(15.5, -70) reference; L31 (15.5, -70)-(14.177, -70) reference; L32 (14.177, -70)-(7.75, -63.374) reference; L33 (7.75, -63.374)-(7.75, -56.626) reference; L34 (7.75, -56.626)-(14.177, -50) reference; L35 (14.177, -50)-(15.5, -50) reference; L36 (15.5, -50)-(15.5, -56) reference; L37 (15.5, -56)-(20, -56) reference; L38 (20, -56)-(20, -24) reference; L39 (20, -24)-(15.5, -24) reference; L40 (15.5, -24)-(15.5, -30) reference; L41 (15.5, -30)-(14.177, -30) reference; L42 (14.177, -30)-(7.75, -23.374) reference; L43 (7.75, -23.374)-(7.75, -16.626) reference; L44 (7.75, -16.626)-(14.177, -10) reference; L45 (14.177, -10)-(15.5, -10) reference; L46 (15.5, -10)-(15.5, -16) reference; L47 (15.5, -16)-(20, -16) reference; L48 (20, -16)-(20, 16) reference; L49 (20, 16)-(15.5, 16) reference; L50 (15.5, 16)-(15.5, 10) reference; L51 (15.5, 10)-(14.177, 10) reference; L52 (14.177, 10)-(7.75, 16.626) reference; L53 (7.75, 16.626)-(7.75, 23.374) reference; L54 (7.75, 23.374)-(14.177, 30) reference; L55 (14.177, 30)-(15.5, 30) reference; L56 (15.5, 30)-(15.5, 24) reference; L57 (15.5, 24)-(20, 24) reference; L58 (20, 24)-(20, 56) reference; L59 (20, 56)-(15.5, 56) reference; L60 (15.5, 56)-(15.5, 50) reference; L61 (15.5, 50)-(14.177, 50) reference; L62 (14.177, 50)-(7.75, 56.626) reference; L63 (7.75, 56.626)-(7.75, 63.374) reference; L64 (7.75, 63.374)-(14.177, 70) reference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; C1 r 3.4 at (0, -60) reference; C2 r 3.4 at (0, -20) reference; C3 r 3.4 at (0, 20) reference; C4 r 3.4 at (0, 60) reference; 1 further point
  constraints: 264 end point, 48 horizontal, 48 vertical, 4 centre point, 177 other
extrude "Extrusion 11-140" sketch "11-140" stored distance "d81" = 10; taper "d82" = 0 deg
sketch "10-164"
  geometry: L1 (-7.75, -25.625)-(-12.125, -30); L2 (-12.125, -30)-(-17, -30); L3 (-17, -30)-(-17, -27); L4 (-17, -27)-(-15.5, -27); L5 (-15.5, -27)-(-15.5, -24); L6 (-15.5, -24)-(-20, -24); L7 (-20, -24)-(-20, -56); L8 (-20, -56)-(-15.5, -56); L9 (-15.5, -56)-(-15.5, -53); L10 (-15.5, -53)-(-17, -53); L11 (-17, -53)-(-17, -50); L12 (-17, -50)-(-12.125, -50); L13 (-12.125, -50)-(-7.75, -54.375); L14 (-7.75, -54.375)-(-7.75, -60); L15 (-7.75, -60)-(-7.75, -65.625); L16 (-7.75, -65.625)-(-12.125, -70); L17 (-12.125, -70)-(-17, -70); L18 (-17, -70)-(-17, -67); L19 (-17, -67)-(-15.5, -67); L20 (-15.5, -67)-(-15.5, -64); L21 (-15.5, -64)-(-20, -64); L22 (-20, -64)-(-20, -77); L23 (-20, -77)-(-17, -80); L24 (-17, -80)-(-4, -80); L25 (-4, -80)-(-4, -75.5); L26 (-4, -75.5)-(-7, -75.5); L27 (-7, -75.5)-(-7, -77); L28 (-7, -77)-(-10, -77); L29 (-10, -77)-(-10, -72.125); L30 (-10, -72.125)-(-5.625, -67.75); L31 (-5.625, -67.75)-(0, -67.75); L32 (0, -67.75)-(5.625, -67.75); L33 (5.625, -67.75)-(10, -72.125); L34 (10, -72.125)-(10, -77); L35 (10, -77)-(7, -77); L36 (7, -77)-(7, -75.5); L37 (7, -75.5)-(4, -75.5); L38 (4, -75.5)-(4, -80); L39 (4, -80)-(17, -80); L40 (17, -80)-(20, -77); L41 (20, -77)-(20, -64); L42 (20, -64)-(15.5, -64); L43 (15.5, -64)-(15.5, -67); L44 (15.5, -67)-(17, -67); L45 (17, -67)-(17, -70); L46 (17, -70)-(12.125, -70); L47 (12.125, -70)-(7.75, -65.625); L48 (7.75, -65.625)-(7.75, -60); L49 (7.75, -60)-(7.75, -54.375); L50 (7.75, -54.375)-(12.125, -50); L51 (12.125, -50)-(17, -50); L52 (17, -50)-(17, -53); L53 (17, -53)-(15.5, -53); L54 (15.5, -53)-(15.5, -56); L55 (15.5, -56)-(20, -56); L56 (20, -56)-(20, -24); L57 (20, -24)-(15.5, -24); L58 (15.5, -24)-(15.5, -27); L59 (15.5, -27)-(17, -27); L60 (17, -27)-(17, -30); L61 (17, -30)-(12.125, -30); L62 (12.125, -30)-(7.75, -25.625); L63 (7.75, -25.625)-(7.75, -20); L64 (7.75, -20)-(7.75, -14.375)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; C1 r 3.4 at (0, -20); C2 r 3.4 at (0, -60); C3 r 3.4 at (0, 20); C4 r 3.4 at (0, 60); 1 further point
  constraints: 428 end point, 4 centre point
extrude "Extrusion 10-164" sketch "10-164" stored distance "d83" = 10; taper "d84" = 0 deg
sketch "11-088"
  geometry: L1 (24, 40)-(37, 40); L2 (37, 40)-(40, 37); L3 (40, 37)-(40, 24); L4 (40, 24)-(35.5, 24); L5 (35.5, 24)-(35.5, 30); L6 (35.5, 30)-(34.177, 30); L7 (34.177, 30)-(27.75, 23.374); L8 (27.75, 23.374)-(27.75, 16.626); L9 (27.75, 16.626)-(34.177, 10); L10 (34.177, 10)-(35.5, 10); L11 (35.5, 10)-(35.5, 16); L12 (35.5, 16)-(40, 16); L13 (40, 16)-(40, -16); L14 (40, -16)-(35.5, -16); L15 (35.5, -16)-(35.5, -10); L16 (35.5, -10)-(34.177, -10); L17 (34.177, -10)-(27.75, -16.626); L18 (27.75, -16.626)-(27.75, -23.374); L19 (27.75, -23.374)-(34.177, -30); L20 (34.177, -30)-(35.5, -30); L21 (35.5, -30)-(35.5, -24); L22 (35.5, -24)-(40, -24); L23 (40, -24)-(40, -37); L24 (40, -37)-(37, -40); L25 (37, -40)-(24, -40); L26 (24, -40)-(24, -35.5); L27 (24, -35.5)-(30, -35.5); L28 (30, -35.5)-(30, -34.177); L29 (30, -34.177)-(23.374, -27.75); L30 (23.374, -27.75)-(16.626, -27.75); L31 (16.626, -27.75)-(10, -34.177); L32 (10, -34.177)-(10, -35.5); L33 (10, -35.5)-(16, -35.5); L34 (16, -35.5)-(16, -40); L35 (16, -40)-(-16, -40); L36 (-16, -40)-(-16, -35.5); L37 (-16, -35.5)-(-10, -35.5); L38 (-10, -35.5)-(-10, -34.177); L39 (-10, -34.177)-(-16.626, -27.75); L40 (-16.626, -27.75)-(-23.374, -27.75); L41 (-23.374, -27.75)-(-30, -34.177); L42 (-30, -34.177)-(-30, -35.5); L43 (-30, -35.5)-(-24, -35.5); L44 (-24, -35.5)-(-24, -40); L45 (-24, -40)-(-37, -40); L46 (-37, -40)-(-40, -37); L47 (-40, -37)-(-40, -24); L48 (-40, -24)-(-35.5, -24); L49 (-35.5, -24)-(-35.5, -30); L50 (-35.5, -30)-(-34.177, -30); L51 (-34.177, -30)-(-27.75, -23.374); L52 (-27.75, -23.374)-(-27.75, -16.626); L53 (-27.75, -16.626)-(-34.177, -10); L54 (-34.177, -10)-(-35.5, -10); L55 (-35.5, -10)-(-35.5, -16); L56 (-35.5, -16)-(-40, -16); L57 (-40, -16)-(-40, 16); L58 (-40, 16)-(-35.5, 16); L59 (-35.5, 16)-(-35.5, 10); L60 (-35.5, 10)-(-34.177, 10); L61 (-34.177, 10)-(-27.75, 16.626); L62 (-27.75, 16.626)-(-27.75, 23.374); L63 (-27.75, 23.374)-(-34.177, 30); L64 (-34.177, 30)-(-35.5, 30)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; C1 r 3.4 at (-20, -20); C2 r 3.4 at (-20, 20); C3 r 3.4 at (20, -20); C4 r 3.4 at (20, 20); 1 further point
  constraints: 240 end point, 4 centre point
extrude "Extrusion 11-088" sketch "11-088" stored distance "d91" = 10; taper "d92" = 0 deg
